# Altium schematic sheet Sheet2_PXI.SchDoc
size A4
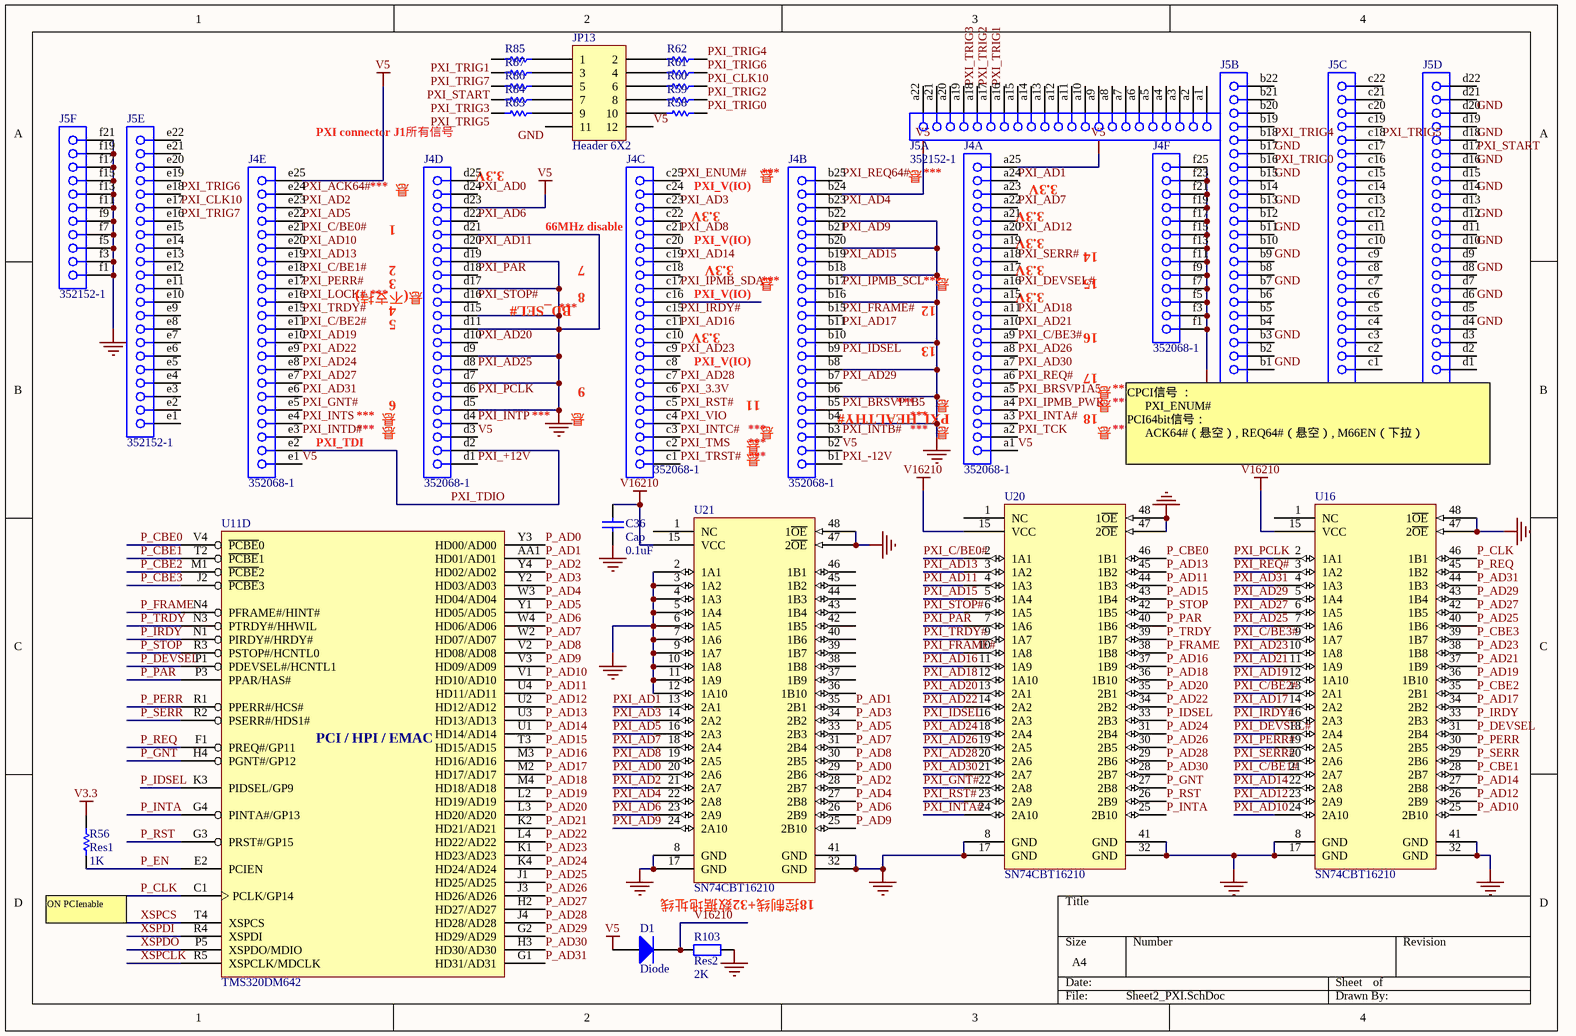
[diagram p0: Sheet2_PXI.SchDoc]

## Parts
C36  Cap  value 0.1uF  [C1608-0603]
D1  Diode  [CR2012-0805]
J4  352068-1  [PCI2-H123]  (parts A,B,C,D,E,F of 6)
J5  352152-1  [PCI2-H121]  (parts A,B,C,D,E,F of 6)
JP13  Header 6X2  [HDR2X6]
R56  Res1  value 1K  [CR1608-0603]
R58  Res1  [CR1608-0603]  (value not drawn)
R59  Res1  [CR1608-0603]  (value not drawn)
R60  Res1  [CR1608-0603]  (value not drawn)
R61  Res1  [CR1608-0603]  (value not drawn)
R62  Res1  [CR1608-0603]  (value not drawn)
R83  Res1  [CR1608-0603]  (value not drawn)
R84  Res1  [CR1608-0603]  (value not drawn)
R85  Res1  [CR1608-0603]  (value not drawn)
R86  Res1  [CR1608-0603]  (value not drawn)
R87  Res1  [CR1608-0603]  (value not drawn)
R103  Res2  value 2K  [C1608-0603]
U11  TMS320DM642  [GNZ548]  (part D of 5)
U16  SN74CBT16210  [SSOP48]
U20  SN74CBT16210  [SSOP48]
U21  SN74CBT16210  [SSOP48]

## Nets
GND: C36.1 J4.b4 J4.b6 J4.b8 J4.b10 J4.b16 J4.b18 J4.b20 J4.b22 J4.d5 J4.d7 J4.d9 J4.d11 J4.d15 J4.d17 J4.d19 J4.d21 J4.f1 J4.f3 J4.f5 J4.f7 J4.f9 J4.f11 J4.f13 J4.f15 J4.f17 J4.f19 J4.f21 J4.f23 J4.f25 J5.b1 J5.b3 J5.b7 J5.b9 J5.b11 J5.b13 J5.b15 J5.b17 J5.d4 J5.d6 J5.d8 J5.d10 J5.d12 J5.d14 J5.d16 J5.d18 J5.d20 J5.f1 J5.f3 J5.f5 J5.f7 J5.f9 J5.f11 J5.f13 J5.f15 J5.f17 J5.f19 J5.f21 JP13.11 R103.2 U16.8(GND) U16.17(GND) U16.32(GND) U16.41(GND) U16.47(2~{OE}) U16.48(1~{OE}) U20.8(GND) U20.17(GND) U20.32(GND) U20.41(GND) U20.47(2~{OE}) U20.48(1~{OE}) U21.2(1A1) U21.3(1A2) U21.4(1A3) U21.5(1A4) U21.6(1A5) U21.7(1A6) U21.8(GND) U21.9(1A7) U21.10(1A8) U21.11(1A9) U21.12(1A10) U21.17(GND) U21.32(GND) U21.41(GND) U21.47(2~{OE}) U21.48(1~{OE})
V3.3: R56.2
V5: D1.1(A) J4.a1 J4.a25 J4.b2 J4.b24 J4.d3 J4.d23 J4.e1 J4.e25 JP13.12
V16210: C36.2 D1.2(K) R103.1 U16.15(VCC) U20.15(VCC) U21.15(VCC)
P_AD0: U11.Y3(HD00/AD00) U21.29(2B6)
P_AD1: U11.AA1(HD01/AD01) U21.35(2B1)
P_AD2: U11.Y4(HD02/AD02) U21.28(2B7)
P_AD3: U11.Y2(HD03/AD03) U21.34(2B2)
P_AD4: U11.W3(HD04/AD04) U21.27(2B8)
P_AD5: U11.Y1(HD05/AD05) U21.33(2B3)
P_AD6: U11.W4(HD06/AD06) U21.26(2B9)
P_AD7: U11.W2(HD07/AD07) U21.31(2B4)
P_AD8: U11.V2(HD08/AD08) U21.30(2B5)
P_AD9: U11.V3(HD09/AD09) U21.25(2B10)
P_AD10: U11.V1(HD10/AD10) U16.25(2B10)
P_AD11: U11.U4(HD11/AD11) U20.44(1B3)
P_AD12: U11.U2(HD12/AD12) U16.26(2B9)
P_AD13: U11.U3(HD13/AD13) U20.45(1B2)
P_AD14: U11.U1(HD14/AD14) U16.27(2B8)
P_AD15: U11.T3(HD15/AD15) U20.43(1B4)
P_AD16: U11.M3(HD16/AD16) U20.37(1B9)
P_AD17: U11.M2(HD17/AD17) U16.34(2B2)
P_AD18: U11.M4(HD18/AD18) U20.36(1B10)
P_AD19: U11.L2(HD19/AD19) U16.36(1B10)
P_AD20: U11.L3(HD20/AD20) U20.35(2B1)
P_AD21: U11.K2(HD21/AD21) U16.37(1B9)
P_AD22: U11.L4(HD22/AD22) U20.34(2B2)
P_AD23: U11.K1(HD23/AD23) U16.38(1B8)
P_AD24: U11.K4(HD24/AD24) U20.31(2B4)
P_AD25: U11.J1(HD25/AD25) U16.40(1B6)
P_AD26: U11.J3(HD26/AD26) U20.30(2B5)
P_AD27: U11.H2(HD27/AD27) U16.42(1B5)
P_AD28: U11.J4(HD28/AD28) U20.29(2B6)
P_AD29: U11.G2(HD29/AD29) U16.43(1B4)
P_AD30: U11.H3(HD30/AD30) U20.28(2B7)
P_AD31: U11.G1(HD31/AD31) U16.44(1B3)
P_CBE0: U11.V4(~{PCBE}0) U20.46(1B1)
P_CBE1: U11.T2(~{PCBE}1) U16.28(2B7)
P_CBE2: U11.M1(~{PCBE}2) U16.35(2B1)
P_CBE3: U11.J2(~{PCBE}3) U16.39(1B7)
P_CLK: U11.C1(PCLK/GP14) U16.46(1B1)
P_DEVSEL: U11.P1(PDEVSEL#/HCNTL1) U16.31(2B4)
P_EN: R56.1 U11.E2(PCIEN)
P_FRAME: U11.N4(PFRAME#/HINT#) U20.38(1B8)
P_GNT: U11.H4(PGNT#/GP12) U20.27(2B8)
P_IDSEL: U11.K3(PIDSEL/GP9) U20.33(2B3)
P_INTA: U11.G4(PINTA#/GP13) U20.25(2B10)
P_IRDY: U11.N1(PIRDY#/HRDY#) U16.33(2B3)
P_PAR: U11.P3(PPAR/HAS#) U20.40(1B6)
P_PERR: U11.R1(PPERR#/HCS#) U16.30(2B5)
P_REQ: U11.F1(PREQ#/GP11) U16.45(1B2)
P_RST: U11.G3(PRST#/GP15) U20.26(2B9)
P_SERR: U11.R2(PSERR#/HDS1#) U16.29(2B6)
P_STOP: U11.R3(PSTOP#/HCNTL0) U20.42(1B5)
P_TRDY: U11.N3(PTRDY#/HHWIL) U20.39(1B7)
PXI_3.3V: J4.c6
PXI_+12V: J4.d1
PXI_-12V: J4.b1
PXI_ACK64#: J4.e24
PXI_AD0: J4.d24 U21.20(2A6)
PXI_AD1: J4.a24 U21.13(2A1)
PXI_AD2: J4.e23 U21.21(2A7)
PXI_AD3: J4.c23 U21.14(2A2)
PXI_AD4: J4.b23 U21.22(2A8)
PXI_AD5: J4.e22 U21.16(2A3)
PXI_AD6: J4.d22 U21.23(2A9)
PXI_AD7: J4.a22 U21.18(2A4)
PXI_AD8: J4.c21 U21.19(2A5)
PXI_AD9: J4.b21 U21.24(2A10)
PXI_AD10: J4.e20 U16.24(2A10)
PXI_AD11: J4.d20 U20.4(1A3)
PXI_AD12: J4.a20 U16.23(2A9)
PXI_AD13: J4.e19 U20.3(1A2)
PXI_AD14: J4.c19 U16.22(2A8)
PXI_AD15: J4.b19 U20.5(1A4)
PXI_AD16: J4.c11 U20.11(1A9)
PXI_AD17: J4.b11 U16.14(2A2)
PXI_AD18: J4.a11 U20.12(1A10)
PXI_AD19: J4.e10 U16.12(1A10)
PXI_AD20: J4.d10 U20.13(2A1)
PXI_AD21: J4.a10 U16.11(1A9)
PXI_AD22: J4.e9 U20.14(2A2)
PXI_AD23: J4.c9 U16.10(1A8)
PXI_AD24: J4.e8 U20.18(2A4)
PXI_AD25: J4.d8 U16.7(1A6)
PXI_AD26: J4.a8 U20.19(2A5)
PXI_AD27: J4.e7 U16.6(1A5)
PXI_AD28: J4.c7 U20.20(2A6)
PXI_AD29: J4.b7 U16.5(1A4)
PXI_AD30: J4.a7 U20.21(2A7)
PXI_AD31: J4.e6 U16.4(1A3)
PXI_BRSVP1A5: J4.a5
PXI_BRSVP1B5: J4.b5
PXI_C/BE0#: J4.e21 U20.2(1A1)
PXI_C/BE1#: J4.e18 U16.21(2A7)
PXI_C/BE2#: J4.e11 U16.13(2A1)
PXI_C/BE3#: J4.a9 U16.9(1A7)
PXI_CLK10: J5.e17 R60.1
PXI_DEVSEL#: J4.a16 U16.18(2A4)
PXI_ENUM#: J4.c25
PXI_FRAME#: J4.b15 U20.10(1A8)
PXI_GNT#: J4.e5 U20.22(2A8)
PXI_IDSEL: J4.b9 U20.16(2A3)
PXI_INTA#: J4.a3 U20.24(2A10)
PXI_INTB#: J4.b3
PXI_INTC#: J4.c3
PXI_INTD#: J4.e3
PXI_INTP: J4.d4
PXI_INTS: J4.e4
PXI_IPMB_PWR: J4.a4
PXI_IPMB_SCL: J4.b17
PXI_IPMB_SDA: J4.c17
PXI_IRDY#: J4.c15 U16.16(2A3)
PXI_LOCK#: J4.e16
PXI_PAR: J4.d18 U20.7(1A6)
PXI_PCLK: J4.d6 U16.2(1A1)
PXI_PERR#: J4.e17 U16.19(2A5)
PXI_REQ64#: J4.b25
PXI_REQ#: J4.a6 U16.3(1A2)
PXI_RST#: J4.c5 U20.23(2A9)
PXI_SERR#: J4.a18 U16.20(2A6)
PXI_START: J5.d17 R86.2
PXI_STOP#: J4.d16 U20.6(1A5)
PXI_TCK: J4.a2
PXI_TDIO: J4.d2 J4.e2
PXI_TMS: J4.c2
PXI_TRDY#: J4.e15 U20.9(1A7)
PXI_TRIG0: J5.b16 R58.1
PXI_TRIG1: J5.a16 R85.2
PXI_TRIG2: J5.a17 R59.1
PXI_TRIG3: J5.a18 R84.2
PXI_TRIG4: J5.b18 R62.1
PXI_TRIG5: J5.c18 R83.2
PXI_TRIG6: J5.e18 R61.1
PXI_TRIG7: J5.e16 R87.2
PXI_TRST#: J4.c1
PXI_VIO: J4.c4
XSPCLK: U11.R5(XSPCLK/MDCLK)
XSPCS: U11.T4(XSPCS)
XSPDI: U11.R4(XSPDI)
XSPDO: U11.P5(XSPDO/MDIO)
NetJP13_1: JP13.1 R85.1
NetJP13_2: JP13.2 R62.2
NetJP13_3: JP13.3 R87.1
NetJP13_4: JP13.4 R61.2
NetJP13_5: JP13.5 R86.1
NetJP13_6: JP13.6 R60.2
NetJP13_7: JP13.7 R84.1
NetJP13_8: JP13.8 R59.2
NetJP13_9: JP13.9 R83.1
NetJP13_10: JP13.10 R58.2

Not connected (* = marked no-connect by the designer): J4 a15 a17 a19 a21 a23 c8 c10 c16 c18 c20 c22 c24 d25; J5 a1 a2 a3 a4 a5 a6 a7 a8 a9 a10 a11 a12 a13 a14 a15 a19 a20 a21 a22 b2 b4 b5 b6 b8 b10 b12 b14 b19 b20 b21 b22 c1 c2 c3 c4 c5 c6 c7 c8 c9 c10 c11 c12 c13 c14 c15 c16 c17 c19 c20 c21 c22 d1 d2 d3 d5 d7 d9 d11 d13 d15 d19 d21 d22 e1 e2 e3 e4 e5 e6 e7 e8 e9 e10 e11 e12 e13 e14 e15 e19 e20 e21 e22; U16 1(NC); U20 1(NC); U21 1(NC) 36(1B10) 37(1B9) 38(1B8) 39(1B7) 40(1B6) 42(1B5) 43(1B4) 44(1B3) 45(1B2) 46(1B1)

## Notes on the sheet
- (near J4) PXI connector J1所有信号
- (near J4) 悬
- (near J4) 3.3V
- (near J4) ***
- ***
- 悬
- 1
- (near J4) 66MHz disable
- (near J4) PXI_V(IO)
- 14
- 2
- 3
- 4
- 5
- (near J4) 悬(不支持)
- BD_SEL#
- 7
- 8
- 12
- 15
- 9
- 13
- 16
- 17
- (near J4) PXI_TDI
- 6
- 11
- (near J4) PXI_HEALTHY#
- 18
- (near J5) CPCI信号 ：
  PXI_ENUM#
  PCI64bit信号：
  ACK64#（悬空）, REQ64#（悬空）, M66EN（下拉）
- (near R56) ON PCIenable
- 18控制线+32数据地址线

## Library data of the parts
C36 = Cap: Capacitor
D1 = Diode: Default Diode; Code - JEDEC: DO-214-AB
J4 = 352068-1: Z-Pack 2mm Hard Metric Type A 110 Position Female PCB Mount Connector; Package Information: Latest Revision: Jul-2000; Positions: 110; Module Length: 50 mm; Mating Polarization: Multi-Purpose Center; Rows Loaded: A, B, D, C, E; PCB Layout: Complies with manufacturer's recommendation.; Drill Size: Corresponds to nominal value.
J5 = 352152-1: Z-Pack 2mm Hard Metric Type B 110 Position Female Daughter Card Connector; Package Information: Latest Revision: Jul-2000; Positions: 110; Module Length: 44 mm; Mating Polarization: None; Rows Loaded: A, B, D, C, E; PCB Layout: Complies with manufacturer's recommendation.; Drill Size: Corresponds to nominal value.
JP13 = Header 6X2: Header, 6-Pin, Dual row
R56 = Res1: Resistor
R58-R62 R83-R87 = Res1: Resistor; Value: 1K
R103 = Res2: Resistor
